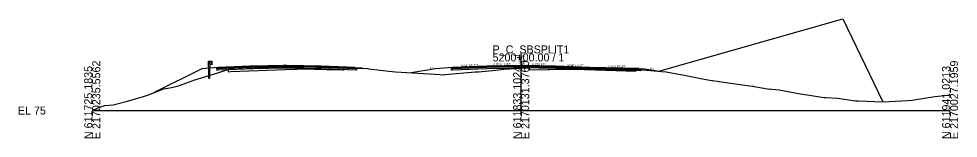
# Model space of a CAD drawing. Extents: x -26 to 1303, y -3010 to 12033.
# Drawn here: x 974.3 to 1302.8, y 1990.3 to 2032.1 of the extents above; entities that cross this region are included whole.
import ezdxf

# ---------------------------------------------------------------- set-up
doc = ezdxf.new("R2010")
doc.units = 0
for name, color, linetype in [('RD_GPK_XS_Cell', 7, 'Continuous'), ('RD_PD_Final_TrvlWay', 7, 'Continuous'), ('RD_Sketch10', 7, 'Continuous'), ('RD_XS_Base', 7, 'Continuous'), ('RD_XS_ExGround', 7, 'Continuous'), ('RD_XS_ExPaveRet', 7, 'Continuous'), ('RD_XS_GR', 7, 'Continuous'), ('RD_XS_Greenside', 7, 'Continuous'), ('RD_XS_Pave', 7, 'Continuous'), ('RD_XS_PaveOvlay_CP', 7, 'Continuous'), ('RD_XS_TieSlope', 7, 'Continuous'), ('RD_XS_TX_Elev_EX', 7, 'Continuous'), ('RD_XS_TX_Elev_PR', 7, 'Continuous'), ('RD_XS_TX_Slope', 7, 'Continuous')]:
    doc.layers.add(name, color=color, linetype=linetype)

msp = doc.modelspace()

# ---------------------------------------------------------------- linework, layer by layer
at = {"layer": 'RD_GPK_XS_Cell'}
for p, q in [((1150, 2000), (1150, 2020)), ((1000, 2000), (1150, 2000)), ((1150, 2000), (1300, 2000))]:
    msp.add_line(p, q, dxfattribs=at)
at = {"layer": 'RD_PD_Final_TrvlWay'}
msp.add_lwpolyline([(1041.13, 2011.23), (1041.13, 2014.83), (1040.63, 2014.79), (1040.63, 2011.23)], dxfattribs=at)
at = {"layer": 'RD_Sketch10'}
msp.add_lwpolyline([(1198.1, 2013.76), (1262.47, 2032.12), (1276.49, 2002.99)], dxfattribs=at)
at = {"layer": 'RD_XS_Base'}
for p, q in [((1043.97, 2014.75), (1043.5, 2014.73)), ((1043.5, 2014.73), (1043.5, 2014.7)), ((1043.5, 2014.7), (1043.5, 2014.23)), ((1043.5, 2014.23), (1043.97, 2014.25)), ((1044, 2014.75), (1043.97, 2014.75)), ((1043.97, 2014.25), (1044, 2014.25)), ((1055.05, 2015.19), (1044, 2014.75)), ((1044, 2014.25), (1055.05, 2014.69)), ((1056, 2015.23), (1055.05, 2015.19)), ((1055.05, 2014.69), (1056, 2014.73)), ((1066.81, 2015.44), (1056, 2015.23)), ((1056, 2014.73), (1066.81, 2014.94)), ((1068, 2015.47), (1066.81, 2015.44)), ((1066.81, 2014.94), (1068, 2014.97)), ((1068, 2015.61), (1068, 2015.63)), ((1068, 2015.63), (1068, 2015.56)), ((1068, 2015.47), (1068, 2015.63)), ((1068, 2015.63), (1068, 2015.63)), ((1068, 2015.63), (1068, 2015.63)), ((1068, 2015.63), (1068, 2014.97)), ((1068, 2015.47), (1068, 2015.61)), ((1068, 2015.56), (1068, 2014.97)), ((1068, 2015.42), (1068, 2015.47)), ((1068, 2014.97), (1068, 2015.47)), ((1068, 2015.47), (1068, 2015.47)), ((1068, 2015.47), (1068, 2015.47)), ((1068, 2015.47), (1068, 2015.47)), ((1080, 2015.23), (1068, 2015.47)), ((1068, 2014.97), (1068, 2015.42)), ((1068, 2014.97), (1068, 2014.97)), ((1068, 2014.97), (1068, 2014.97)), ((1068, 2014.97), (1080, 2014.73)), ((1092, 2014.75), (1080, 2015.23)), ((1080, 2014.73), (1092.5, 2014.23)), ((1082, 2015.15), (1082, 2015.15)), ((1082, 2014.65), (1082, 2014.65)), ((1092.5, 2014.73), (1092, 2014.75)), ((1092, 2014.75), (1092, 2014.75)), ((1092.5, 2014.23), (1092.5, 2014.73)), ((1092.5, 2014.73), (1092.5, 2014.73)), ((1126, 2014.74), (1125.5, 2014.72)), ((1125.5, 2014.72), (1125.5, 2014.72)), ((1125.5, 2014.72), (1125.5, 2014.22)), ((1125.5, 2014.22), (1126, 2014.24)), ((1138, 2015.22), (1126, 2014.74)), ((1126, 2014.74), (1126, 2014.74)), ((1126, 2014.24), (1138, 2014.72)), ((1126, 2014.24), (1126, 2014.24)), ((1136, 2015.14), (1136, 2015.14)), ((1136, 2014.64), (1136, 2014.64)), ((1150, 2015.46), (1138, 2015.22)), ((1138, 2014.72), (1150, 2014.96)), ((1150, 2014.96), (1150, 2015.62)), ((1150, 2015.62), (1150, 2015.62)), ((1150, 2015.62), (1150, 2015.62)), ((1150, 2015.62), (1150, 2015.46)), ((1150, 2015.46), (1150, 2015.46)), ((1150, 2015.46), (1162, 2015.22)), ((1150, 2015.46), (1150, 2015.46)), ((1150, 2014.96), (1150, 2015.46)), ((1150, 2015.46), (1150, 2015.46)), ((1150, 2015.46), (1150, 2015.46)), ((1162, 2014.72), (1150, 2014.96)), ((1150, 2014.96), (1150, 2014.96)), ((1150, 2014.96), (1150, 2014.96)), ((1162, 2015.22), (1162, 2015.22)), ((1162, 2015.22), (1174, 2014.74)), ((1174, 2014.24), (1162, 2014.72)), ((1162, 2014.72), (1162, 2014.72)), ((1174, 2014.74), (1174, 2014.74)), ((1174, 2014.74), (1191.3, 2014.4)), ((1191.8, 2013.89), (1174, 2014.24)), ((1174, 2014.24), (1174, 2014.24)), ((1191.3, 2014.4), (1191.3, 2014.4)), ((1191.3, 2014.4), (1191.8, 2014.39)), ((1191.8, 2014.39), (1191.8, 2014.39)), ((1191.8, 2014.39), (1191.8, 2013.89))]:
    msp.add_line(p, q, dxfattribs=at)
at = {"layer": 'RD_XS_ExGround'}
msp.add_lwpolyline([(1000, 2000.23), (1001.12, 2000.45), (1002.41, 2001.18), (1004.42, 2001.78), (1007.31, 2002), (1012.35, 2003.33), (1015.5, 2004.27), (1017.53, 2004.8), (1019.65, 2005.5), (1022.67, 2006.67), (1024.97, 2007.56), (1027.11, 2007.96), (1029.81, 2008.48), (1033.69, 2009.91), (1034.93, 2010.36), (1035.48, 2010.64), (1044.26, 2013.32), (1047.12, 2014.26), (1047.57, 2014.35), (1070.84, 2015.25), (1071.51, 2015.28), (1072.43, 2015.32), (1073.47, 2015.29), (1074.03, 2015.28), (1082.88, 2015.1), (1088.08, 2015), (1091.53, 2014.87), (1096.31, 2014.71), (1096.66, 2014.64), (1097.83, 2014.5), (1103.77, 2013.78), (1106.07, 2013.49), (1119.82, 2012.68), (1121.51, 2012.58), (1122.46, 2012.53), (1123.3, 2012.6), (1133.94, 2013.56), (1135.13, 2013.49), (1141.18, 2014.13), (1143.95, 2014.5), (1150.03, 2014.86), (1151.74, 2014.93), (1152.76, 2014.99), (1159.49, 2015.1), (1159.88, 2015.11), (1167.98, 2015.25), (1176.02, 2014.98), (1190.08, 2014.51), (1199.08, 2013.66), (1200.73, 2013.49), (1205.68, 2012.58), (1206.42, 2012.45), (1213.41, 2011.12), (1216.52, 2010.53), (1216.7, 2010.5), (1216.88, 2010.47), (1224.06, 2009.5), (1230.81, 2008.55), (1230.89, 2008.55), (1231.15, 2008.51), (1231.44, 2008.45), (1236.9, 2007.52), (1237.12, 2007.55), (1237.49, 2007.49), (1240.18, 2007.21), (1247.64, 2005.83), (1250.05, 2005.5), (1255.1, 2004.72), (1255.91, 2004.59), (1256.6, 2004.6), (1260.64, 2004.35), (1266.89, 2003.43), (1267.9, 2003.38), (1276.49, 2002.99), (1280.91, 2003.23), (1285.3, 2003.5), (1286.59, 2003.6), (1286.77, 2003.61), (1287.39, 2003.7), (1294.67, 2004.97), (1299.23, 2005.34), (1300, 2005.66)], dxfattribs=at)
at = {"layer": 'RD_XS_ExPaveRet'}
for points in [[(1087.59, 2015.01), (1082.59, 2015.1), (1081.96, 2015.12), (1073.47, 2015.29), (1072.43, 2015.32), (1072.43, 2015.32), (1072.43, 2015.32), (1072.43, 2015.32), (1072.43, 2015.32), (1071.51, 2015.28), (1070.84, 2015.25), (1048.35, 2014.38), (1047.57, 2014.35), (1047.57, 2014.35), (1047.57, 2013.65), (1047.57, 2013.6), (1047.57, 2013.6), (1048.35, 2013.63), (1070.84, 2014.5), (1071.51, 2014.53), (1072.43, 2014.57), (1072.43, 2014.57), (1072.43, 2014.57), (1072.43, 2014.57), (1072.43, 2014.57), (1073.47, 2014.54), (1081.96, 2014.37), (1082.59, 2014.35), (1087.59, 2014.26), (1087.9, 2014.25), (1088.08, 2014.25), (1088.08, 2014.37), (1088.08, 2015), (1087.9, 2015), (1087.59, 2015.01)], [(1087.59, 2015.01), (1082.59, 2015.1), (1081.96, 2015.12), (1073.47, 2015.29), (1072.43, 2015.32), (1072.43, 2015.32), (1072.43, 2015.32), (1072.43, 2015.32), (1072.43, 2015.32), (1071.51, 2015.28), (1070.84, 2015.25), (1048.35, 2014.38), (1047.57, 2014.35), (1047.57, 2014.35), (1047.57, 2013.65), (1047.57, 2013.6), (1047.57, 2013.6), (1048.35, 2013.63), (1070.84, 2014.5), (1071.51, 2014.53), (1072.43, 2014.57), (1072.43, 2014.57), (1072.43, 2014.57), (1072.43, 2014.57), (1072.43, 2014.57), (1073.47, 2014.54), (1081.96, 2014.37), (1082.59, 2014.35), (1087.59, 2014.26), (1087.9, 2014.25), (1088.08, 2014.25), (1088.08, 2014.37), (1088.08, 2015), (1087.9, 2015), (1087.59, 2015.01)], [(1176.02, 2014.98), (1167.98, 2015.25), (1167.98, 2015.25), (1159.88, 2015.11), (1159.88, 2015.11), (1159.49, 2015.1), (1152.76, 2014.99), (1152.76, 2014.99), (1152.76, 2014.24), (1152.76, 2014.24), (1152.76, 2014.24), (1159.49, 2014.35), (1159.88, 2014.36), (1159.88, 2014.36), (1167.98, 2014.5), (1167.98, 2014.5), (1176.02, 2014.23), (1176.02, 2014.23), (1190.08, 2013.76), (1190.08, 2013.76), (1190.08, 2014.51), (1176.02, 2014.98), (1176.02, 2014.98)], [(1176.02, 2014.98), (1167.98, 2015.25), (1159.88, 2015.11), (1159.49, 2015.1), (1152.76, 2014.99), (1152.76, 2014.99), (1152.76, 2014.24), (1152.76, 2014.24), (1159.49, 2014.35), (1159.88, 2014.36), (1167.98, 2014.5), (1176.02, 2014.23), (1190.08, 2013.76), (1190.08, 2014.51), (1176.02, 2014.98)]]:
    msp.add_lwpolyline(points, dxfattribs=at)
at = {"layer": 'RD_XS_GR'}
for p, q in [((1040.63, 2014.79), (1040.63, 2017.23)), ((1040.63, 2017.23), (1040.88, 2017.23)), ((1040.88, 2017.23), (1041.13, 2017.23)), ((1041.13, 2017.23), (1041.13, 2014.83)), ((1041.13, 2016.06), (1041.13, 2017.23)), ((1041.13, 2017.23), (1041.8, 2017.23)), ((1041.8, 2017.23), (1041.8, 2016.06)), ((1041.81, 2017.21), (1041.8, 2017.23)), ((1041.8, 2017.23), (1041.8, 2017.16)), ((1042.07, 2016.94), (1041.81, 2017.21)), ((1041.13, 2014.83), (1040.63, 2014.79)), ((1041.8, 2016.06), (1041.13, 2016.06)), ((1041.8, 2017.16), (1041.8, 2016.06)), ((1041.8, 2016.65), (1042.05, 2016.92)), ((1041.81, 2016.63), (1041.8, 2016.65)), ((1041.8, 2016.06), (1042.05, 2016.34)), ((1042.07, 2016.35), (1041.81, 2016.63)), ((1042.05, 2016.92), (1042.07, 2016.94)), ((1042.05, 2016.34), (1042.07, 2016.35))]:
    msp.add_line(p, q, dxfattribs=at)
at = {"layer": 'RD_XS_Greenside'}
for p, q in [((1038.32, 2014.61), (1021.69, 2006.29)), ((1094, 2014.91), (1094.88, 2014.76)), ((1120, 2014.58), (1111.52, 2013.17)), ((1193.3, 2014.56), (1198.1, 2013.76))]:
    msp.add_line(p, q, dxfattribs=at)
at = {"layer": 'RD_XS_Pave'}
for p, q in [((1055.05, 2015.51), (1044, 2015.06)), ((1055.05, 2015.35), (1044, 2014.91)), ((1044, 2014.91), (1055.05, 2015.35)), ((1044, 2014.75), (1055.05, 2015.19)), ((1044, 2015.06), (1044, 2015.05)), ((1044, 2015.05), (1044, 2014.91)), ((1044, 2014.91), (1044, 2014.9)), ((1044, 2014.9), (1044, 2014.75)), ((1056, 2015.54), (1055.05, 2015.51)), ((1056, 2015.39), (1055.05, 2015.35)), ((1055.05, 2015.35), (1056, 2015.39)), ((1055.05, 2015.19), (1056, 2015.23)), ((1066.81, 2015.76), (1056, 2015.54)), ((1066.81, 2015.6), (1056, 2015.39)), ((1056, 2015.39), (1066.81, 2015.6)), ((1056, 2015.23), (1066.81, 2015.44)), ((1068, 2015.79), (1066.81, 2015.76)), ((1068, 2015.63), (1066.81, 2015.6)), ((1066.81, 2015.6), (1068, 2015.63)), ((1066.81, 2015.44), (1068, 2015.47)), ((1080, 2015.55), (1068, 2015.79)), ((1068, 2015.79), (1068, 2015.79)), ((1068, 2015.79), (1068, 2015.79)), ((1068, 2015.61), (1068, 2015.63)), ((1068, 2015.63), (1068, 2015.61)), ((1068, 2015.47), (1068, 2015.63)), ((1068, 2015.63), (1068, 2015.63)), ((1068, 2015.63), (1068, 2015.63)), ((1068, 2015.63), (1068, 2015.63)), ((1068, 2015.63), (1068, 2015.63)), ((1068, 2015.63), (1080, 2015.39)), ((1080, 2015.39), (1068, 2015.63)), ((1068, 2015.63), (1068, 2015.63)), ((1068, 2015.63), (1068, 2015.63)), ((1068, 2015.63), (1068, 2015.47)), ((1068, 2015.47), (1068, 2015.61)), ((1068, 2015.61), (1068, 2015.47)), ((1068, 2015.47), (1068, 2015.47)), ((1068, 2015.47), (1068, 2015.47)), ((1068, 2015.47), (1080, 2015.23)), ((1092, 2015.07), (1080, 2015.55)), ((1080, 2015.39), (1092, 2014.91)), ((1092, 2014.91), (1080, 2015.39)), ((1080, 2015.23), (1092, 2014.75)), ((1082, 2015.47), (1082, 2015.47)), ((1082, 2015.31), (1082, 2015.31)), ((1082, 2015.31), (1082, 2015.31)), ((1082, 2015.15), (1082, 2015.15)), ((1092, 2014.91), (1092, 2015.07)), ((1092, 2015.07), (1092, 2015.07)), ((1092, 2014.75), (1092, 2014.91)), ((1092, 2014.91), (1092, 2014.91)), ((1138, 2015.54), (1126, 2015.06)), ((1138, 2015.38), (1126, 2014.9)), ((1126, 2014.9), (1138, 2015.38)), ((1126, 2014.74), (1138, 2015.22)), ((1126, 2015.06), (1126, 2015.06)), ((1126, 2015.06), (1126, 2014.9)), ((1126, 2014.9), (1126, 2014.9)), ((1126, 2014.9), (1126, 2014.74)), ((1136, 2015.46), (1136, 2015.46)), ((1136, 2015.3), (1136, 2015.3)), ((1136, 2015.3), (1136, 2015.3)), ((1136, 2015.14), (1136, 2015.14)), ((1150, 2015.78), (1138, 2015.54)), ((1150, 2015.62), (1138, 2015.38)), ((1138, 2015.38), (1150, 2015.62)), ((1138, 2015.22), (1150, 2015.46)), ((1162, 2015.54), (1150, 2015.78)), ((1150, 2015.78), (1150, 2015.78)), ((1150, 2015.78), (1150, 2015.78)), ((1150, 2015.46), (1150, 2015.62)), ((1150, 2015.62), (1150, 2015.62)), ((1150, 2015.62), (1150, 2015.62)), ((1150, 2015.62), (1150, 2015.62)), ((1150, 2015.62), (1150, 2015.62)), ((1150, 2015.62), (1162, 2015.38)), ((1162, 2015.38), (1150, 2015.62)), ((1150, 2015.62), (1150, 2015.62)), ((1150, 2015.62), (1150, 2015.62)), ((1150, 2015.62), (1150, 2015.62)), ((1150, 2015.62), (1150, 2015.46)), ((1150, 2015.46), (1150, 2015.46)), ((1150, 2015.46), (1150, 2015.46)), ((1150, 2015.46), (1150, 2015.46)), ((1150, 2015.46), (1162, 2015.22)), ((1174, 2015.06), (1162, 2015.54)), ((1162, 2015.54), (1162, 2015.54)), ((1162, 2015.38), (1162, 2015.38)), ((1162, 2015.38), (1174, 2014.9)), ((1174, 2014.9), (1162, 2015.38)), ((1162, 2015.38), (1162, 2015.38)), ((1162, 2015.22), (1162, 2015.22)), ((1162, 2015.22), (1174, 2014.74)), ((1191.3, 2014.72), (1174, 2015.06)), ((1174, 2015.06), (1174, 2015.06)), ((1174, 2014.9), (1174, 2014.9)), ((1174, 2014.9), (1191.3, 2014.56)), ((1191.3, 2014.56), (1174, 2014.9)), ((1174, 2014.9), (1174, 2014.9)), ((1174, 2014.74), (1191.3, 2014.4)), ((1174, 2014.74), (1174, 2014.74)), ((1191.3, 2014.56), (1191.3, 2014.72)), ((1191.3, 2014.72), (1191.3, 2014.72)), ((1191.3, 2014.4), (1191.3, 2014.56)), ((1191.3, 2014.56), (1191.3, 2014.56))]:
    msp.add_line(p, q, dxfattribs=at)
at = {"layer": 'RD_XS_PaveOvlay_CP'}
for p, q in [((1044, 2015.06), (1056, 2015.54)), ((1056, 2015.54), (1068, 2015.79)), ((1068, 2015.79), (1080, 2015.55)), ((1080, 2015.55), (1092, 2015.07)), ((1138, 2015.54), (1126, 2015.06)), ((1136, 2015.46), (1136, 2015.46)), ((1150, 2015.78), (1138, 2015.54)), ((1162, 2015.54), (1150, 2015.78)), ((1150, 2015.78), (1150, 2015.78)), ((1150, 2015.78), (1150, 2015.78)), ((1174, 2015.06), (1162, 2015.54)), ((1162, 2015.54), (1162, 2015.54)), ((1191.3, 2014.72), (1174, 2015.06)), ((1174, 2015.06), (1174, 2015.06))]:
    msp.add_line(p, q, dxfattribs=at)
at = {"layer": 'RD_XS_TieSlope'}
for p, q in [((1044, 2015.06), (1038.32, 2014.61)), ((1092, 2015.07), (1094, 2014.91)), ((1126, 2015.06), (1120, 2014.58)), ((1191.3, 2014.72), (1193.3, 2014.56))]:
    msp.add_line(p, q, dxfattribs=at)

# ---------------------------------------------------------------- texts
at = {"layer": 'RD_GPK_XS_Cell'}
for s, p in [('P_C_SBSPLIT1', (1140, 2020)), ('5200+00.00 / 1', (1140, 2017.2)), ('EL 75', (974, 1998.6))]:
    msp.add_text(s, height=2.8, dxfattribs=at).set_placement(p)
for s, p in [('E 2170235.5562', (1002.8, 1990)), ('E 2170131.3760', (1152.8, 1990)), ('E 2170027.1959', (1302.8, 1990)), ('N 611725.1835', (1000, 1990)), ('N 611833.1024', (1150, 1990)), ('N 611941.0213', (1300, 1990))]:
    msp.add_text(s, height=2.8, rotation=90, dxfattribs=at).set_placement(p)
at = {"layer": 'RD_XS_TX_Elev_EX'}
msp.add_text('89.83', height=0.6, rotation=90, dxfattribs=at).set_placement((1149.66, 2016.5))
at = {"layer": 'RD_XS_TX_Elev_PR'}
msp.add_text('90.78', height=1, rotation=90, dxfattribs=at).set_placement((1151.21, 2015.98))
at = {"layer": 'RD_XS_TX_Slope'}
for s, rotation, p in [('6:1', 9.4642, (1118.13, 2014.33)), ('0.040 FT./FT.', 2.2906, (1128.93, 2015.28)), ('0.020 FT./FT.', 1.1458, (1140.27, 2015.75)), ('0.020 FT./FT.', 358.8542, (1153.94, 2015.8)), ('0.040 FT./FT.', 357.7094, (1165.94, 2015.48)), ('0.020 FT./FT.', 358.8542, (1180.59, 2015.03)), ('6:1', 350.5377, (1195.05, 2014.32))]:
    msp.add_text(s, height=0.75, rotation=rotation, dxfattribs=at).set_placement(p)

doc.saveas('drawing.dxf')
